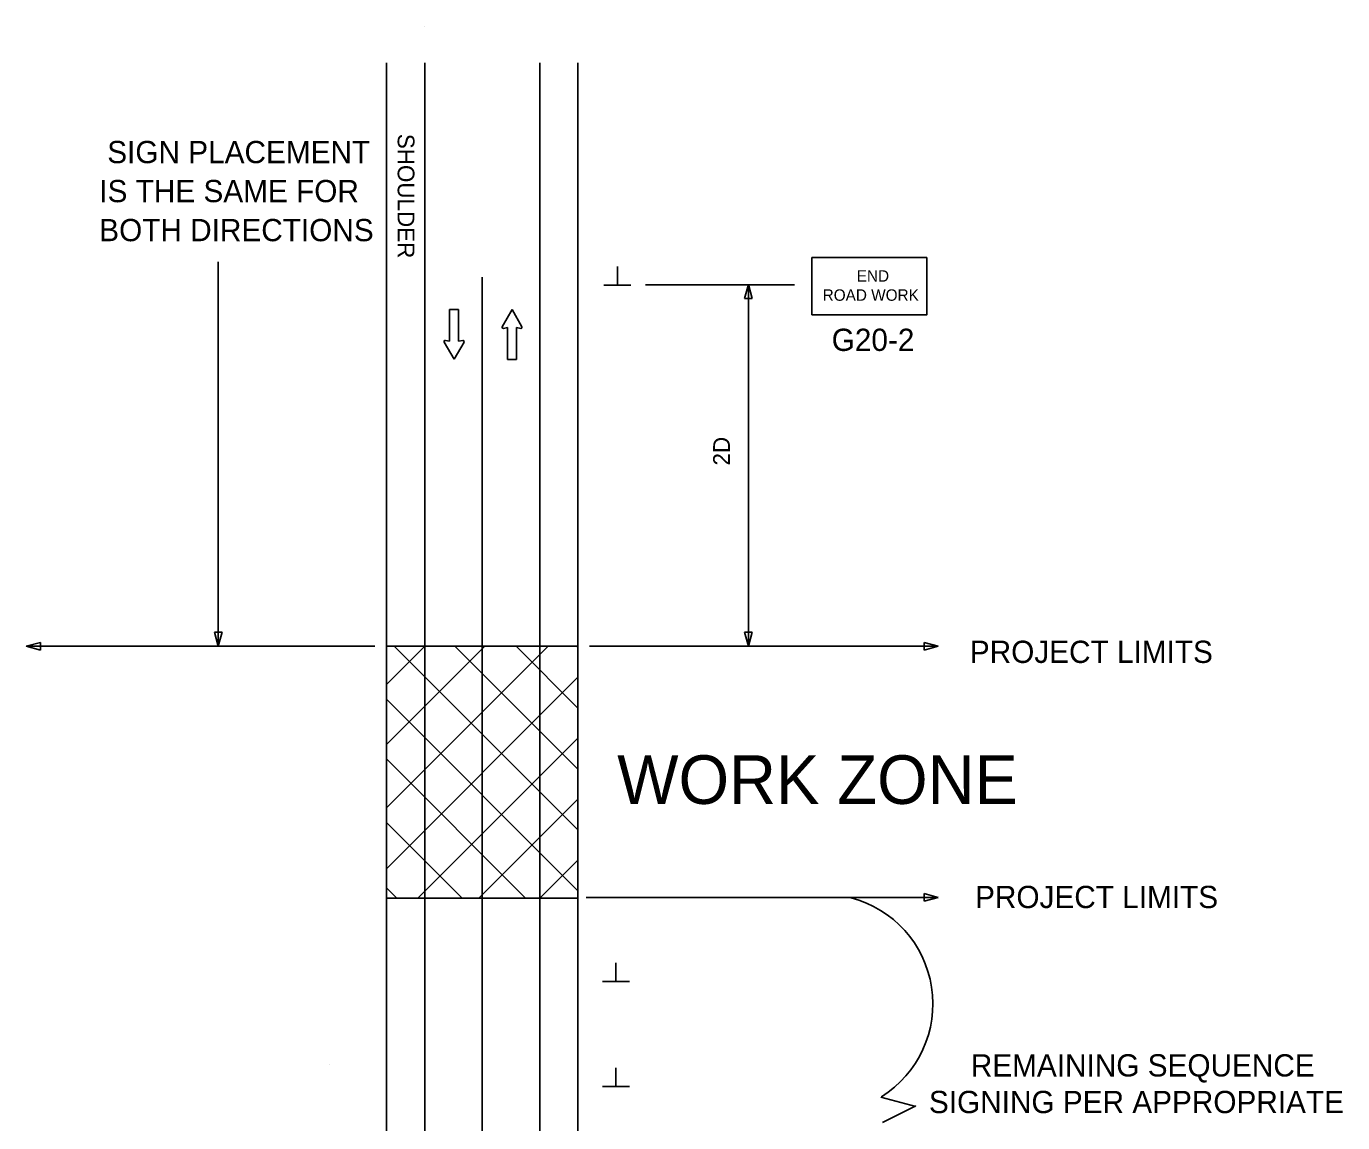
# Model space of a CAD drawing. Extents: x 19023 to 20747, y 5121 to 6119.
# Drawn here: x 19073 to 19623, y 5661 to 6119 of the extents above; entities that cross this region are included whole.
import ezdxf

# ---------------------------------------------------------------- set-up
doc = ezdxf.new("R2010")
doc.units = 0
for name, color, linetype in [('BORDER', 7, 'Continuous'), ('MT_SCRATCH_LEVEL_E', 7, 'Continuous'), ('PAVT_EDGE_EX', 7, 'Continuous'), ('TRAFFIC_SIGNS_PR', 7, 'Continuous'), ('TYPICAL_TEXT_DIMEN_PR', 7, 'Continuous')]:
    doc.layers.add(name, color=color, linetype=linetype)

msp = doc.modelspace()

# ---------------------------------------------------------------- linework, layer by layer
at = {"layer": 'BORDER'}
msp.add_line((19199.105, 5685.504), (19199.105, 5685.504), dxfattribs=at)
at = {"layer": 'MT_SCRATCH_LEVEL_E'}
for p, q in [((19253.189, 6000.952), (19249.447, 6000.952)), ((19249.447, 6000.952), (19249.447, 5987.694)), ((19253.189, 6000.952), (19249.447, 6000.952)), ((19249.447, 6000.952), (19249.447, 5987.694)), ((19253.189, 5987.694), (19253.189, 6000.952)), ((19253.189, 5987.694), (19253.189, 6000.952)), ((19275.531, 6000.951), (19271.42, 5993.71)), ((19275.531, 6000.951), (19271.42, 5993.71)), ((19279.678, 5993.71), (19275.531, 6000.951)), ((19279.678, 5993.71), (19275.531, 6000.951)), ((19271.902, 5993.026), (19273.679, 5993.342)), ((19271.902, 5993.026), (19273.679, 5993.342)), ((19273.679, 5993.342), (19273.679, 5980.084)), ((19273.679, 5993.342), (19273.679, 5980.084)), ((19277.421, 5980.084), (19277.421, 5993.342)), ((19277.421, 5993.342), (19279.199, 5993.026)), ((19277.421, 5980.084), (19277.421, 5993.342)), ((19277.421, 5993.342), (19279.199, 5993.026)), ((19247.19, 5987.326), (19251.337, 5980.085)), ((19247.19, 5987.326), (19251.337, 5980.085)), ((19249.447, 5987.694), (19247.669, 5988.01)), ((19249.447, 5987.694), (19247.669, 5988.01)), ((19251.337, 5980.085), (19255.448, 5987.326)), ((19251.337, 5980.085), (19255.448, 5987.326)), ((19254.966, 5988.01), (19253.189, 5987.694)), ((19254.966, 5988.01), (19253.189, 5987.694)), ((19273.679, 5980.084), (19277.421, 5980.084)), ((19273.679, 5980.084), (19277.421, 5980.084))]:
    msp.add_line(p, q, dxfattribs=at)
for centre, start, end in [((19271.828, 5993.486), 150.42484, 279.96381), ((19271.828, 5993.486), 150.42484, 279.96381), ((19279.268, 5993.487), 260.03619, 29.77312), ((19279.268, 5993.487), 260.03619, 29.77312), ((19247.6, 5987.549), 80.03619, 209.77312), ((19247.6, 5987.549), 80.03619, 209.77312), ((19255.04, 5987.55), 330.42484, 99.96381), ((19255.04, 5987.55), 330.42484, 99.96381)]:
    msp.add_arc(centre, 0.463, start, end, dxfattribs=at)
at = {"layer": 'PAVT_EDGE_EX'}
for p, q in [((19223.086, 6104.026), (19223.086, 5261.047)), ((19239.086, 6104.026), (19239.086, 5261.047)), ((19287.086, 6104.026), (19287.086, 5261.047)), ((19303.086, 6104.026), (19303.086, 5261.047)), ((19239.086, 6014.455), (19239.086, 5261.047)), ((19263.086, 6014.455), (19263.086, 5261.047)), ((19303.086, 5860.205), (19223.086, 5860.205)), ((19223.113, 5792.747), (19290.571, 5860.205)), ((19223.17, 5819.322), (19263.82, 5859.972)), ((19223.176, 5844.408), (19238.768, 5860)), ((19303.086, 5783.445), (19226.359, 5860.172)), ((19303.086, 5808.901), (19251.54, 5860.447)), ((19303.086, 5834.356), (19277.379, 5860.063)), ((19287.086, 5860.676), (19287.086, 5754.897)), ((19303.086, 5859.812), (19302.693, 5860.205)), ((19303.086, 5754.897), (19303.086, 5860.205)), ((19223.087, 5767.266), (19303.086, 5847.265)), ((19303.022, 5758.053), (19223.133, 5837.942)), ((19236.329, 5755.052), (19303.086, 5821.809)), ((19281.216, 5755.023), (19223.138, 5813.101)), ((19261.652, 5754.919), (19303.086, 5796.353)), ((19254.737, 5754.958), (19223.091, 5786.604)), ((19287.086, 5754.897), (19303.086, 5770.897)), ((19223.086, 5754.897), (19303.057, 5754.897)), ((19227.216, 5755.123), (19223.111, 5759.228)), ((19287.086, 5754.897), (19303.086, 5754.897)), ((19287.086, 5754.897), (19287.086, 5754.897))]:
    msp.add_line(p, q, dxfattribs=at)
for points in [[(19239.086, 6014.455), (19239.086, 5989.455)], [(19263.086, 6014.455), (19263.086, 5989.455)], [(19263.086, 5914.455), (19263.086, 5889.455)], [(19263.086, 5714.455), (19263.086, 5689.455)]]:
    msp.add_lwpolyline(points, dxfattribs=at)
at = {"layer": 'TRAFFIC_SIGNS_PR'}
msp.add_line((19239.086, 6119.208), (19239.086, 6119.208), dxfattribs=at)
msp.add_line((19239.086, 6119.208), (19239.086, 6119.208), dxfattribs=at)
msp.add_lwpolyline([(19400.831, 5998.613), (19448.831, 5998.613), (19448.831, 6022.613), (19400.831, 6022.613)], close=True, dxfattribs=at)
at = {"layer": 'TYPICAL_TEXT_DIMEN_PR'}
for p, q in [((19152.746, 6020.888), (19152.746, 5860.357)), ((19319.563, 6011.039), (19319.563, 6018.824)), ((19319.563, 6011.039), (19313.938, 6011.039)), ((19325.188, 6011.039), (19319.563, 6011.039)), ((19331.301, 6011.246), (19393.615, 6011.246)), ((19372.743, 6005.484), (19374.314, 6011.346)), ((19374.304, 6011.141), (19374.304, 5860.357)), ((19374.314, 6011.346), (19375.885, 6005.484)), ((19374.314, 6005.484), (19372.743, 6005.484)), ((19375.885, 6005.484), (19374.314, 6005.484)), ((19152.735, 5866.042), (19151.164, 5866.042)), ((19151.164, 5866.042), (19152.735, 5860.18)), ((19152.735, 5860.18), (19154.306, 5866.042)), ((19154.306, 5866.042), (19152.735, 5866.042)), ((19374.315, 5860.18), (19372.744, 5866.042)), ((19372.744, 5866.042), (19374.315, 5866.042)), ((19374.315, 5866.042), (19375.886, 5866.042)), ((19375.886, 5866.042), (19374.315, 5860.18)), ((19078.388, 5861.764), (19072.526, 5860.193)), ((19072.526, 5860.193), (19078.388, 5858.622)), ((19218.208, 5860.193), (19073.404, 5860.193)), ((19078.388, 5860.193), (19078.388, 5861.764)), ((19078.388, 5858.622), (19078.388, 5860.193)), ((19307.964, 5860.193), (19453.646, 5860.193)), ((19447.784, 5860.193), (19447.784, 5861.764)), ((19447.784, 5861.764), (19453.646, 5860.193)), ((19453.646, 5860.193), (19447.784, 5858.622)), ((19447.784, 5858.622), (19447.784, 5860.193)), ((19306.479, 5755.292), (19453.646, 5755.292)), ((19447.784, 5755.292), (19447.784, 5756.863)), ((19447.784, 5756.863), (19453.646, 5755.292)), ((19453.646, 5755.292), (19447.784, 5753.721)), ((19447.784, 5753.721), (19447.784, 5755.292)), ((19318.945, 5720.103), (19318.945, 5727.888)), ((19318.945, 5720.103), (19313.32, 5720.103)), ((19324.57, 5720.103), (19318.945, 5720.103)), ((19318.946, 5676.281), (19318.946, 5684.066)), ((19318.946, 5676.281), (19313.321, 5676.281)), ((19324.571, 5676.281), (19318.946, 5676.281)), ((19429.668, 5671.774), (19444.31, 5667.914)), ((19444.31, 5668.188), (19430.283, 5661.176))]:
    msp.add_line(p, q, dxfattribs=at)
msp.add_arc((19405.569, 5710.817), 45.823, 302.15629, 75.25172, dxfattribs=at)

# ---------------------------------------------------------------- texts
at = {"layer": 'TRAFFIC_SIGNS_PR'}
for s, height, p in [('SIGN PLACEMENT', 9.3, (19106.342, 6062.034)), ('IS THE SAME FOR', 9.3, (19103.024, 6045.734)), ('BOTH DIRECTIONS', 9.3, (19103.003, 6029.434)), ('END', 4.789, (19419.581, 6012.523)), ('ROAD WORK', 4.789, (19405.342, 6004.541)), ('G20-2', 9.3, (19409.115, 5983.589)), ('PROJECT LIMITS', 9.3, (19466.853, 5853.237)), ('PROJECT LIMITS', 9.3, (19469.041, 5750.817)), ('REMAINING SEQUENCE', 9.3, (19467.254, 5680.457)), ('SIGNING PER APPROPRIATE', 9.3, (19449.754, 5665.157))]:
    msp.add_text(s, height=height, dxfattribs=at).set_placement(p)
at = {"layer": 'TYPICAL_TEXT_DIMEN_PR'}
for s, rotation, p in [('SHOULDER', 270, (19227.724, 6074.3)), ('2D', 90, (19366.578, 5935.723))]:
    msp.add_text(s, height=7, rotation=rotation, dxfattribs=at).set_placement(p)
msp.add_text('WORK ZONE', height=20.309, dxfattribs=at).set_placement((19319.473, 5794.349))

doc.saveas('drawing.dxf')
